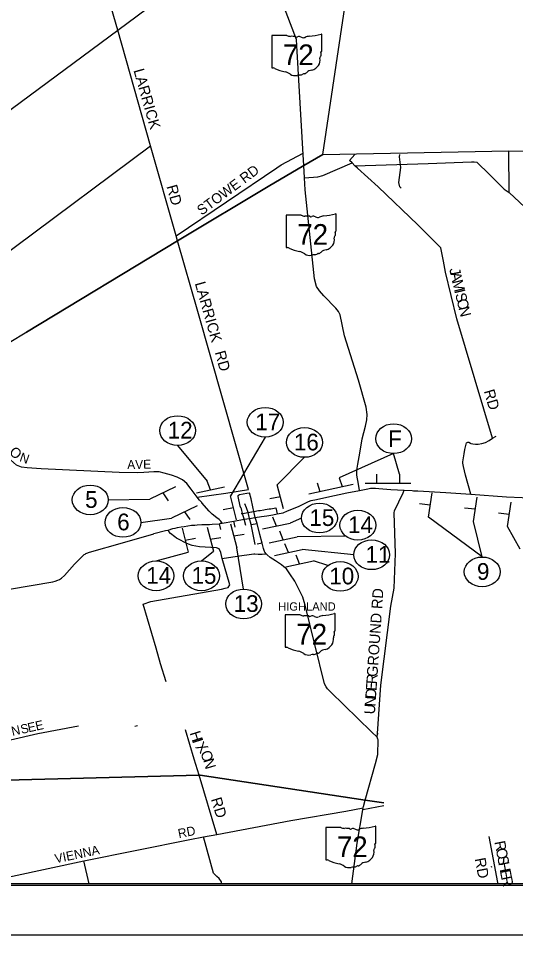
# Model space of a CAD drawing. Extents: x 0 to 784, y 0 to 440.
# Drawn here: x 266.5 to 367.9, y 0 to 186.8 of the extents above; entities that cross this region are included whole.
import ezdxf

# ---------------------------------------------------------------- set-up
doc = ezdxf.new("R2010")
doc.units = 0
for name, color, linetype in [('Default', 7, 'Continuous'), ('SH_Border', 7, 'Continuous'), ('SH_Cut_Line', 7, 'Continuous')]:
    doc.layers.add(name, color=color, linetype=linetype)

msp = doc.modelspace()

# ---------------------------------------------------------------- linework, layer by layer
at = {"layer": 'Default'}
for p, q in [((318.14, 183.17), (318.14, 176.77)), ((321.23, 183.28), (318.24, 183.28)), ((328.33, 180.09), (328.33, 183.44)), ((328.33, 180.09), (328.33, 180.09)), ((321.07, 146.55), (321.07, 140.15)), ((324.15, 146.66), (321.17, 146.66)), ((331.25, 143.47), (331.25, 146.82)), ((331.25, 143.47), (331.25, 143.47)), ((316.82, 101.4), (309.73, 89.42)), ((298.96, 99.71), (304.96, 92.45)), ((324.82, 97.29), (319.28, 91.68)), ((342.99, 98.06), (331.9, 93.09)), ((344.18, 93.84), (342.99, 98.06)), ((339.52, 93.84), (339.52, 92.02)), ((344.18, 93.84), (344.18, 92.02)), ((305.66, 90.66), (304.96, 92.45)), ((320.54, 86.79), (319.28, 91.68)), ((325.71, 89.84), (334.72, 91.84)), ((327.4, 92.09), (327.97, 90.34)), ((331.9, 93.09), (332.47, 91.34)), ((337.18, 92.02), (346.51, 92.02)), ((341.85, 92.02), (341.85, 92.02)), ((298.54, 91.27), (293.31, 88.77)), ((295.92, 90.02), (297.02, 88.45)), ((302.83, 90.06), (308.49, 91.26)), ((330.22, 90.84), (330.22, 90.84)), ((350.08, 85.09), (350.82, 90.05)), ((284.81, 88.61), (293.31, 88.77)), ((310.99, 84.53), (309.73, 89.42)), ((319.91, 89.24), (317.76, 88.86)), ((350.45, 87.57), (348.27, 87.79)), ((359.27, 84.23), (360, 89.19)), ((366.19, 83.18), (366.93, 88.15)), ((302.97, 87.42), (297.74, 84.92)), ((300.36, 86.17), (301.45, 84.59)), ((310.36, 86.98), (308.21, 86.6)), ((359.63, 86.71), (357.46, 86.93)), ((291.48, 84.03), (297.74, 84.92)), ((319.1, 83.29), (318.4, 85.08)), ((324.2, 84.92), (321.93, 83.89)), ((361.05, 76.98), (350.08, 85.09)), ((361.05, 76.98), (359.27, 84.23)), ((366.56, 85.66), (364.38, 85.89)), ((299.86, 82.85), (301.11, 77.96)), ((304.99, 83.04), (306.25, 78.15)), ((309.77, 83.72), (311.03, 78.83)), ((316.27, 82.69), (321.93, 83.89)), ((320.47, 80.47), (319.77, 82.26)), ((368.77, 78.57), (366.19, 83.18)), ((300.48, 80.4), (302.63, 80.78)), ((305.62, 80.59), (307.77, 80.97)), ((310.4, 81.27), (312.55, 81.65)), ((317.64, 79.87), (323.3, 81.07)), ((333.06, 81.25), (323.3, 81.07)), ((312.42, 70.43), (311.03, 78.83)), ((318.7, 77.27), (324.37, 78.48)), ((321.54, 77.88), (320.84, 79.67)), ((334.85, 77.43), (324.37, 78.48)), ((294.56, 76.16), (301.11, 77.96)), ((303.83, 76.16), (306.25, 78.15)), ((323.82, 75.59), (323.12, 77.38)), ((320.99, 74.99), (326.66, 76.19)), ((329.57, 75.22), (326.66, 76.19)), ((320.88, 65.09), (320.88, 58.69)), ((323.96, 65.2), (320.98, 65.2)), ((331.07, 62.01), (331.07, 65.36)), ((331.06, 62.01), (331.07, 62.01)), ((329.14, 21.75), (329.14, 15.35)), ((332.23, 21.86), (329.24, 21.86)), ((339.33, 18.67), (339.33, 22.02)), ((339.33, 18.67), (339.33, 18.67)), ((392.02, 10.38), (128.62, 10.38))]:
    msp.add_line(p, q, dxfattribs=at)
msp.add_lwpolyline([(31.33, 429.99), (465.77, 429.99), (465.77, 10.05), (31.33, 10.05)], close=True, dxfattribs=at)
for points in [[(323.21, 182.43), (315.65, 202.22), (314.37, 204.87), (313.25, 207.38), (312.12, 209.93), (311.85, 210.45), (311.28, 211.22), (309.95, 212.69), (299.4, 224.01), (293.97, 229.72), (280.12, 245.85), (276.05, 250.6)], [(286.74, 184.37), (277.84, 214.9), (271.69, 210.64), (271.3, 210.44), (270.93, 210.44), (270.45, 210.49), (245.32, 221.77), (245.17, 221.81)], [(286.74, 184.37), (314.37, 204.87)], [(328.56, 159.01), (334.86, 201.37)], [(252.68, 159.16), (286.74, 184.37)], [(298.95, 141.4), (298.67, 142.42), (293.4, 160.8), (286.74, 184.37)], [(324.58, 159.01), (323.31, 179.99), (323.21, 182.43)], [(238.35, 119.77), (293.4, 160.8)], [(328.56, 159.01), (324.71, 156.77), (317.42, 152.51), (299.29, 141.61), (298.95, 141.4), (256.26, 115.59)], [(328.56, 159.01), (324.71, 156.77), (317.42, 152.51), (299.29, 141.61), (298.95, 141.4), (268.13, 122.77)], [(268.13, 122.77), (298.95, 141.4), (299.29, 141.61), (317.42, 152.51), (324.71, 156.77), (328.56, 159.01)], [(328.56, 159.01), (324.71, 156.77), (317.42, 152.51), (299.29, 141.61), (298.95, 141.4), (268.13, 122.77)], [(320.06, 156.92), (324.55, 159.26)], [(324.71, 156.77), (324.58, 159.01)], [(328.56, 159.01), (366.45, 159.73), (396.22, 159.13), (423.03, 158.58)], [(355.86, 125.51), (353.59, 135.03), (353.16, 137.24), (352.61, 139.97), (347.89, 144.66), (339.84, 152.44), (335.62, 156.23), (335.11, 156.72), (334.51, 157.31), (334.01, 157.8), (335.11, 159.01)], [(344.54, 152.16), (344.25, 152.41), (344.03, 153.29), (344.44, 156.38), (344.31, 157.44), (344.17, 158.51), (344.22, 159.01)], [(400.1, 109.53), (400.24, 109.81), (400.01, 110.26), (396.65, 111.87), (392.19, 114.32), (390.61, 115.73), (388.29, 117.96), (387.43, 119.3), (386.82, 120.91), (386.23, 124.05), (385.81, 125.27), (384.94, 126.32), (382.89, 127.43), (381.69, 128.03), (381.15, 128.49), (381.8, 130.74), (383.06, 135.1), (382.88, 135.84), (381.56, 137.15), (372.84, 145.35), (366.54, 151.28), (366.45, 159.73)], [(319.17, 156.31), (320.06, 156.92), (320.06, 156.92)], [(324.84, 154.24), (327.55, 154.45), (328.57, 154.72), (334.51, 157.31)], [(335.11, 156.72), (350.04, 157.17), (358.85, 157.52), (359.43, 157.53), (359.95, 157.47), (362.55, 154.91), (365.51, 151.95), (366.54, 151.28)], [(298.67, 142.42), (319.17, 156.31), (319.17, 156.31)], [(336.04, 90.54), (335.84, 91.79), (335.52, 93.68), (335.49, 94.64), (335.7, 95.87), (336.09, 98.12), (336.56, 101.03), (337.23, 103.67), (337.5, 104.93), (337.57, 106.01), (337.42, 107.49), (335.86, 113.03), (332.97, 122.05), (332.07, 126.32), (331.73, 127.01), (331.19, 127.67), (328.79, 130.22), (327.88, 131.22), (327.28, 132.13), (326.89, 133.64), (324.97, 151.84), (324.84, 154.24), (324.71, 156.77)], [(303.06, 127), (298.95, 141.4)], [(313.41, 90.76), (303.06, 127)], [(363.16, 101.22), (355.86, 125.51)], [(303.45, 88.57), (302.92, 89.19), (301.74, 90.77), (300.85, 91.93), (299.93, 92.71), (298.86, 93.27), (297.7, 93.64), (296.21, 94.08), (295.21, 94.32), (294.09, 94.31), (292.08, 94.21), (290.78, 94.14), (287.05, 94.23), (271.13, 94.94), (268.28, 95.18), (267.12, 95.31), (266.15, 95.66), (259.9, 101.1), (248.09, 110.65)], [(358.7, 100.14), (359.16, 100.01), (359.7, 99.96), (360.19, 100), (360.98, 100.11), (361.7, 100.33), (362.49, 100.73), (363.16, 101.22), (363.9, 101.61)], [(357.53, 98.89), (357.7, 99.68), (357.78, 99.95), (357.82, 100.25), (358.08, 100.4), (358.35, 100.36), (358.63, 100.16), (358.7, 100.14)], [(358.71, 89.79), (357.66, 93.66), (357.24, 95.39), (357.11, 96.08), (357.09, 96.36), (357.34, 97.97), (357.53, 98.89)], [(302.92, 89.19), (308.79, 89.97), (313.41, 90.76)], [(311.4, 89.57), (311.55, 89.69), (313.09, 89.97), (313.59, 90.03)], [(314.79, 85.02), (314.5, 86.26), (314.27, 87.22), (313.92, 88.8), (313.59, 90.03)], [(320.46, 86.01), (320.63, 86.06), (321.25, 86.31), (323.71, 87.36), (324.84, 87.89), (325.62, 88.28), (326.21, 88.47), (327.24, 88.71), (329.34, 89.19), (333.45, 90.04), (336.04, 90.54)], [(336.04, 90.54), (337.75, 90.9), (338.27, 90.98), (339.27, 90.98), (339.97, 90.93)], [(339.97, 90.93), (342.44, 90.74), (345.15, 90.6), (346.76, 90.51), (347.03, 90.49)], [(342.42, 66.98), (343.13, 70.65), (343.37, 77.66), (343.07, 86), (343.18, 86.41), (344.95, 90.06), (345.15, 90.6)], [(347.03, 90.49), (347.93, 90.46), (353.66, 90.11), (358.71, 89.79), (366.02, 89.27), (369.16, 89.08), (370.05, 89.03), (371.59, 88.89), (371.86, 88.87)], [(341, 26.87), (337.2, 27.44), (303.55, 32.49), (303.35, 32.48), (258.73, 31.34), (252.96, 31.39), (250.33, 32.34), (184.83, 56.05), (169.46, 61.61), (188.74, 73.63), (212.87, 88.69)], [(308.04, 83.9), (307.78, 84.25), (307.41, 84.59), (306.92, 84.98), (305.98, 85.73), (305.41, 86.31), (303.92, 88.02), (303.87, 88.08), (303.45, 88.57)], [(311.95, 86.82), (311.94, 86.85), (311.7, 87.33), (311.3, 89.31), (311.31, 89.5), (311.4, 89.57)], [(314.76, 79.5), (313.93, 83.61), (313.61, 84.84), (313.31, 86.06), (313.03, 87.02), (312.64, 87.84)], [(311.91, 85.83), (312.2, 85.86), (313.31, 86.06), (314.05, 86.18)], [(312.54, 84.66), (312.54, 84.66), (312.2, 85.86), (311.95, 86.82)], [(314.05, 86.18), (314.11, 86.19), (314.5, 86.26), (315.44, 86.42), (315.76, 86.46), (316.53, 86.61), (316.78, 86.64), (317.65, 86.78), (317.95, 86.82), (318.99, 86.98), (319.28, 85.74)], [(314.79, 85.02), (316.03, 85.22), (317.17, 85.38), (318.38, 85.58), (319.28, 85.74), (319.66, 85.84), (320.07, 85.9), (320.46, 86.01)], [(305.47, 83.63), (305.97, 83.65), (307.52, 83.73), (307.8, 83.84), (308.04, 83.9), (310.39, 84.3), (312.54, 84.66), (313.61, 84.84), (314.79, 85.02)], [(310.67, 83.04), (310.39, 84.28)], [(312.86, 83.42), (312.54, 84.66)], [(315.72, 81.55), (315.14, 83.77), (314.79, 85.02)], [(294.08, 81.73), (294.14, 81.75), (296.46, 82.37), (297.04, 82.47), (297.98, 82.76), (298.45, 82.87)], [(308.05, 76.68), (307.75, 77.88), (307.46, 78.62), (306.87, 78.86), (303.39, 79.05), (301.89, 79.34), (301.15, 79.6), (300.56, 79.87), (299.27, 80.53), (298.7, 80.84), (298.37, 81.06), (297.5, 81.77), (297.2, 82.15), (297.04, 82.47)], [(298.45, 82.87), (298.96, 82.99), (299.67, 83.12), (300.32, 83.22), (301.78, 83.44), (302.49, 83.49)], [(302.49, 83.49), (302.97, 83.52), (303.92, 83.59), (305.47, 83.63)], [(307.79, 82.61), (307.52, 83.73)], [(313.97, 83.62), (315.14, 83.77)], [(273.5, 71.94), (274, 72.07), (274.57, 72.25), (274.88, 72.38), (275.29, 72.64), (275.91, 73.2), (277.96, 75.49), (278.93, 76.5), (279.94, 77.48), (280.11, 77.58), (280.28, 77.69), (280.48, 77.78), (280.98, 77.97), (287.69, 79.85), (294.08, 81.73)], [(316.69, 78.08), (316.6, 78.28), (316.46, 78.68), (316.17, 79.78), (315.72, 81.55)], [(316.17, 79.78), (315.16, 79.58)], [(296.61, 51.54), (295.45, 55.2), (294.58, 58.4), (291.95, 67.33), (293.49, 67.88), (307.93, 70.4), (308.68, 70.64), (309.27, 70.78), (309.62, 71.31), (308.05, 76.68), (311.1, 77.13)], [(311.1, 77.13), (314.49, 77.62), (314.71, 77.62), (315.41, 77.57), (316.2, 77.56), (317.02, 77.62)], [(320.61, 75), (320.13, 75.4), (318.89, 76.16), (317.8, 76.86), (317.19, 77.4), (317.02, 77.62), (316.74, 77.96), (316.69, 78.08)], [(324.94, 67.16), (324.77, 67.87), (324.48, 68.76), (322.82, 72.08), (321.83, 73.53), (321.14, 74.55), (320.61, 75)], [(151.92, 50.67), (160.67, 51.86), (169.13, 53.18), (172.73, 53.8), (181.11, 55.3), (184.36, 55.97), (184.83, 56.05), (193.87, 57.67), (202.27, 59.24), (211.56, 60.88), (223.42, 63.02), (230.19, 64.31), (238.93, 65.91), (244.75, 67.02), (246.32, 67.31), (250.33, 67.93), (256.18, 68.96), (273.5, 71.94)], [(339.85, 39.7), (339.8, 39.85), (339.62, 40.25), (338.46, 41.32), (330.11, 49.5), (329.51, 50.1), (329.23, 50.53), (328.89, 51.15), (324.94, 67.16)], [(340.39, 50.87), (342.42, 66.98)], [(339.62, 40.25), (339.73, 40.98), (340.39, 50.87)], [(250.1, 36.81), (259.23, 38.43), (270.46, 40.97), (278.78, 42.57)], [(290.22, 42.52), (290.79, 42.63)], [(302.36, 35.79), (302.36, 35.79), (300.58, 41.73)], [(334.5, 10.38), (335.54, 18.64), (336.71, 25.41), (336.79, 25.85), (336.84, 26.13), (337.2, 27.44), (339.28, 34.88), (339.79, 36.69), (339.85, 39.7)], [(339.73, 40.98), (339.85, 41)], [(306.97, 20.45), (303.35, 32.48), (302.36, 35.79)], [(258.73, 31.34), (303.35, 32.48), (303.55, 32.49), (337.2, 27.44), (341, 26.87)], [(341, 26.28), (336.71, 25.41)], [(257.97, 10.38), (279.82, 15.02), (301.48, 19.39), (304.2, 19.91), (306.97, 20.45), (322.05, 23.3), (333.25, 25.2), (336.79, 25.85)], [(307.89, 10.38), (307.9, 10.8), (307.41, 11.48), (306.93, 11.88), (306.29, 12.53), (304.2, 19.91)], [(364.31, 10.38), (364.24, 10.66), (362.44, 20)], [(280.94, 10.38), (279.82, 15.02)], [(362.99, 13.72), (362.92, 13.88)]]:
    msp.add_lwpolyline(points, dxfattribs=at)
for centre, major_axis, start_param, end_param in [((318.26, 183.19), (0.118, 0), 1.712693, 3.28349), ((321.94, 184.03), (1.14, 0), 4.042523, 4.731795), ((322.32, 179.69), (4.11, 0), 1.404758, 1.657858), ((323.25, 183.22), (0.33, 0), 3.836095, 5.185415), ((323.73, 182.48), (0.686, 0), 0.950623, 2.079405), ((326.08, 181.33), (2.17, 0), 1.699011, 2.107814), ((324.7, 192.02), (10.8, 0), 4.814394, 5.042369), ((328.22, 183.46), (0.113, 0), 6.141152, 7.989035), ((324.62, 183.5), (0.826, 0), 4.081561, 5.145723), ((328.3, 179.85), (0.175, 0), 1.883978, 3.671073), ((327.19, 179.42), (1.05, 0), 5.934695, 6.695948), ((328.21, 180.08), (0.121, 0), 5.05454, 6.418171), ((325.31, 178.26), (2.7, 0), 5.101752, 6.440018), ((328.73, 178.69), (0.766, 0), 2.387724, 3.262537), ((318.26, 176.76), (0.119, 0), 3.00124, 4.508301), ((318.28, 177.41), (0.908, 0), 4.665946, 4.897461), ((318.46, 176.4), (0.328, 0), 0.519207, 1.627899), ((322.6, 182.15), (7.8, 0), 4.195997, 4.488961), ((320.28, 173.89), (2.44, 0), 0.823519, 1.323587), ((324.57, 176.15), (0.873, 0), 4.937069, 5.64225), ((326.44, 174.97), (1.48, 0), 1.647645, 2.488434), ((322.91, 176.37), (1.55, 0), 4.026481, 4.996735), ((323.81, 174.15), (1.27, 0), 1.495662, 1.94098), ((323.92, 175.89), (0.825, 0), 4.691044, 5.507374), ((324.67, 175.27), (0.232, 0), 1.147584, 2.315152), ((321.19, 146.56), (0.118, 0), 1.712693, 3.28349), ((324.86, 147.4), (1.14, 0), 4.042523, 4.731795), ((325.24, 143.07), (4.11, 0), 1.404758, 1.657858), ((326.17, 146.6), (0.33, 0), 3.836095, 5.185415), ((326.66, 145.86), (0.686, 0), 0.950623, 2.079405), ((327.55, 146.87), (0.826, 0), 4.081561, 5.145723), ((329, 144.7), (2.17, 0), 1.699011, 2.107814), ((327.63, 155.39), (10.8, 0), 4.814394, 5.042369), ((331.14, 146.83), (0.113, 0), 6.141152, 7.989035), ((328.23, 141.64), (2.7, 0), 5.101752, 6.440018), ((331.66, 142.07), (0.766, 0), 2.387724, 3.262537), ((331.23, 143.22), (0.175, 0), 1.883978, 3.671073), ((330.11, 142.8), (1.05, 0), 5.934695, 6.695948), ((331.13, 143.46), (0.121, 0), 5.05454, 6.418171), ((321.19, 140.13), (0.119, 0), 3.00124, 4.508301), ((321.21, 140.79), (0.908, 0), 4.665946, 4.897461), ((321.39, 139.78), (0.328, 0), 0.519207, 1.627899), ((325.53, 145.53), (7.8, 0), 4.195997, 4.488961), ((323.2, 137.27), (2.44, 0), 0.823519, 1.323587), ((325.84, 139.74), (1.55, 0), 4.026481, 4.996735), ((326.74, 137.53), (1.27, 0), 1.495662, 1.94098), ((326.85, 139.27), (0.825, 0), 4.691044, 5.507374), ((327.6, 138.65), (0.232, 0), 1.147584, 2.315152), ((327.5, 139.53), (0.873, 0), 4.937069, 5.64225), ((329.37, 138.35), (1.48, 0), 1.647645, 2.488434), ((327.44, 73.93), (10.8, 0), 4.814394, 5.042369), ((330.95, 65.37), (0.113, 0), 6.141152, 7.989035), ((321, 65.1), (0.118, 0), 1.712693, 3.28349), ((324.67, 65.94), (1.14, 0), 4.042523, 4.731795), ((325.05, 61.6), (4.11, 0), 1.404758, 1.657858), ((325.99, 65.14), (0.33, 0), 3.836095, 5.185415), ((326.47, 64.4), (0.686, 0), 0.950623, 2.079405), ((327.36, 65.41), (0.826, 0), 4.081561, 5.145723), ((328.82, 63.24), (2.17, 0), 1.699011, 2.107814), ((331.04, 61.76), (0.175, 0), 1.883978, 3.671073), ((329.92, 61.34), (1.05, 0), 5.934695, 6.695948), ((330.94, 62), (0.121, 0), 5.05454, 6.418171), ((328.04, 60.18), (2.7, 0), 5.101752, 6.440018), ((331.47, 60.61), (0.766, 0), 2.387724, 3.262537), ((321, 58.67), (0.119, 0), 3.00124, 4.508301), ((321.02, 59.33), (0.908, 0), 4.665946, 4.897461), ((321.2, 58.32), (0.328, 0), 0.519207, 1.627899), ((325.34, 64.07), (7.8, 0), 4.195997, 4.488961), ((329.18, 56.89), (1.48, 0), 1.647645, 2.488434), ((323.01, 55.81), (2.44, 0), 0.823519, 1.323587), ((325.65, 58.28), (1.55, 0), 4.026481, 4.996735), ((326.55, 56.07), (1.27, 0), 1.495662, 1.94098), ((326.66, 57.8), (0.825, 0), 4.691044, 5.507374), ((327.41, 57.18), (0.232, 0), 1.147584, 2.315152), ((327.31, 58.06), (0.873, 0), 4.937069, 5.64225), ((329.26, 21.76), (0.118, 0), 1.712693, 3.28349), ((332.94, 22.61), (1.14, 0), 4.042523, 4.731795), ((333.32, 18.27), (4.11, 0), 1.404758, 1.657858), ((334.25, 21.8), (0.33, 0), 3.836095, 5.185415), ((334.74, 21.06), (0.686, 0), 0.950623, 2.079405), ((335.62, 22.07), (0.826, 0), 4.081561, 5.145723), ((337.08, 19.91), (2.17, 0), 1.699011, 2.107814), ((335.7, 30.59), (10.8, 0), 4.814394, 5.042369), ((339.22, 22.03), (0.113, 0), 6.141152, 7.989035), ((336.31, 16.84), (2.7, 0), 5.101752, 6.440018), ((339.74, 17.27), (0.766, 0), 2.387724, 3.262537), ((339.3, 18.42), (0.175, 0), 1.883978, 3.671073), ((338.19, 18), (1.05, 0), 5.934695, 6.695948), ((339.21, 18.66), (0.121, 0), 5.05454, 6.418171), ((329.26, 15.33), (0.119, 0), 3.00124, 4.508301), ((329.28, 15.99), (0.908, 0), 4.665946, 4.897461), ((329.47, 14.98), (0.328, 0), 0.519207, 1.627899), ((333.6, 20.73), (7.8, 0), 4.195997, 4.488961), ((331.28, 12.47), (2.44, 0), 0.823519, 1.323587), ((333.92, 14.95), (1.55, 0), 4.026481, 4.996735), ((334.81, 12.73), (1.27, 0), 1.495662, 1.94098), ((334.92, 14.47), (0.825, 0), 4.691044, 5.507374), ((335.67, 13.85), (0.232, 0), 1.147584, 2.315152), ((335.57, 14.73), (0.873, 0), 4.937069, 5.64225), ((337.45, 13.55), (1.48, 0), 1.647645, 2.488434)]:
    msp.add_ellipse(centre, major_axis=major_axis, ratio=0.82844, start_param=start_param, end_param=end_param, dxfattribs=at)
for centre in [(316.82, 104.43), (298.96, 102.74), (324.82, 100.32), (342.99, 101.09), (281.15, 88.61), (327.86, 84.92), (287.82, 84.03), (335.71, 83.46), (338.51, 77.43), (361.05, 73.94), (294.56, 73.13), (303.83, 73.13), (332.08, 73.02), (312.42, 67.4)]:
    msp.add_ellipse(centre, major_axis=(3.66, 0), ratio=0.82844, dxfattribs=at)
at = {"layer": 'SH_Border'}
msp.add_lwpolyline([(30, 430), (670, 430), (670, 10), (30, 10)], close=True, dxfattribs=at)
at = {"layer": 'SH_Cut_Line'}
msp.add_lwpolyline([(0, 0), (680, 0), (680, 440), (0, 440)], close=True, dxfattribs=at)

# ---------------------------------------------------------------- texts
at = {"layer": 'Default'}
for s, height, p in [('72', 4.219, (320.42, 177.22)), ('72', 4.219, (323.35, 140.6)), ('17', 3.406, (314.8, 102.81)), ('12', 3.406, (296.95, 101.12)), ('F', 3.41, (341.87, 99.38)), ('16', 3.406, (322.67, 98.7)), ('5', 3.41, (280.1, 86.99)), ('15', 3.406, (325.83, 83.3)), ('6', 3.41, (286.64, 82.41)), ('14', 3.406, (333.7, 81.84)), ('11', 3.406, (337.26, 75.81)), ('14', 3.406, (292.56, 71.51)), ('15', 3.406, (301.8, 71.51)), ('10', 3.406, (329.88, 71.4)), ('9', 3.41, (359.98, 72.32)), ('13', 3.406, (310.4, 65.78)), ('72', 4.219, (323.16, 59.14)), ('72', 4.219, (331.42, 15.8))]:
    msp.add_text(s, height=height, dxfattribs=at).set_placement(p)
for s, height, rotation, p in [('LARRICK', 2.194, 285.8978, (289.94, 176.17)), ('STOWE RD', 2.064, 36.7083, (303.87, 146.52)), ('RD', 2.194, 285.5227, (296.67, 152.51)), ('J', 2.19, 281.6052, (354.32, 135.68)), ('A', 2.19, 283.4377, (354.5, 134.78)), ('LARRICK', 2.194, 285.8981, (302.44, 132.76)), ('M', 2.19, 283.6129, (354.88, 133.21)), ('I', 2.19, 283.6161, (355.35, 131.27)), ('S', 2.19, 283.6068, (355.52, 130.54)), ('O', 2.19, 283.6132, (355.81, 129.34)), ('N', 2.19, 283.609, (356.19, 127.77)), ('RD', 2.194, 285.5216, (306.51, 118.69)), ('RD', 2.194, 286.0895, (361.35, 110.79)), ('O', 2.09, 319.957, (264.45, 98.1)), ('N', 1.91, 340.8055, (266.58, 96.52)), ('AVE', 1.819, 1.0348, (288.7, 94.89)), ('GROUND RD', 2.195, 86.0685, (339.69, 52.49)), ('HIGHLAND', 1.696, 0, (319.46, 66.04)), ('R', 2.19, 86.0682, (339.59, 51)), ('E', 2.19, 86.0683, (339.49, 49.64)), ('D', 2.19, 86.0687, (339.38, 48.05)), ('U', 2.19, 86.0687, (339.16, 44.85)), ('N', 2.19, 86.0687, (339.27, 46.45)), ('S', 1.86, 12.4948, (267.16, 40.91)), ('E', 1.86, 12.4921, (268.59, 41.23)), ('E', 1.86, 12.4921, (270.17, 41.58)), ('N', 1.86, 12.4944, (265.29, 40.5)), ('H', 2.19, 287.3299, (301.41, 41.12)), ('I', 2.19, 287.4367, (301.89, 39.57)), ('X', 2.15, 309.8638, (302.47, 38.22)), ('O', 2.19, 293.5074, (303.5, 37.01)), ('N', 2.19, 286.3746, (304.14, 35.56)), ('RD', 2.194, 286.7918, (305.72, 27.62)), ('RD', 1.853, 11.1005, (299.22, 19.67)), ('R', 2.19, 280.722, (363.52, 18.92)), ('VIENNA', 1.857, 11.7012, (274.12, 14.55)), ('O', 2.19, 280.7199, (363.8, 17.44)), ('RD', 2.195, 280.698, (359.51, 15.47)), ('S', 2.19, 280.7232, (364.1, 15.86)), ('H', 2.19, 280.7241, (364.33, 14.65)), ('E', 2.19, 280.767, (364.63, 13.07)), ('R', 2.19, 282.2216, (364.89, 11.68))]:
    msp.add_text(s, height=height, rotation=rotation, dxfattribs=at).set_placement(p)

doc.saveas('drawing.dxf')
